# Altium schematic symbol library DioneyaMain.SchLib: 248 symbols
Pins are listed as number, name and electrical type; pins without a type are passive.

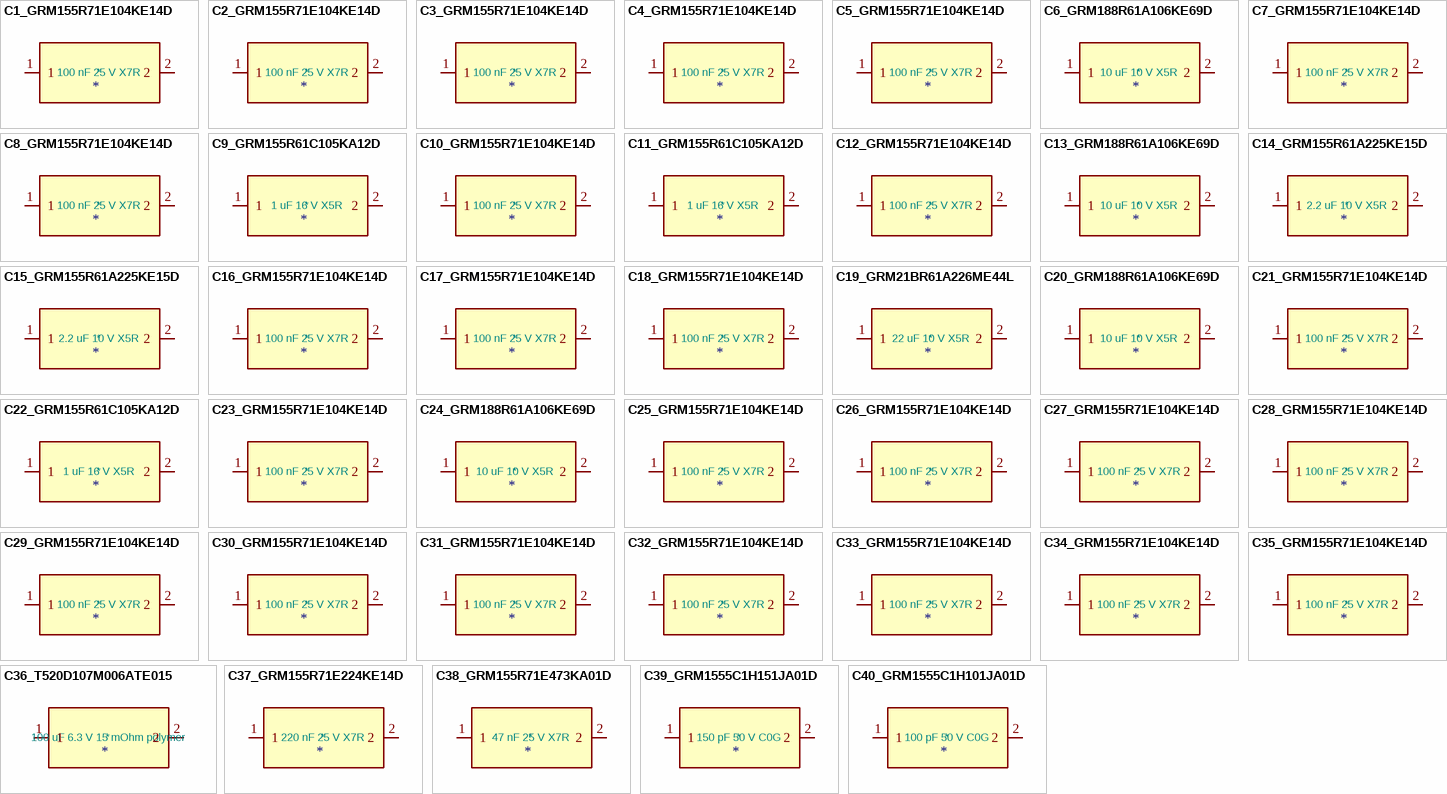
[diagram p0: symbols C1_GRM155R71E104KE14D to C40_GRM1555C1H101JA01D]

## C1_GRM155R71E104KE14D
designator *  value 100 nF 25 V X7R
footprint C_0402_1005Metric
pins: 1, 2

## C2_GRM155R71E104KE14D
designator *  value 100 nF 25 V X7R
footprint C_0402_1005Metric
pins: 1, 2

## C3_GRM155R71E104KE14D
designator *  value 100 nF 25 V X7R
footprint C_0402_1005Metric
pins: 1, 2

## C4_GRM155R71E104KE14D
designator *  value 100 nF 25 V X7R
footprint C_0402_1005Metric
pins: 1, 2

## C5_GRM155R71E104KE14D
designator *  value 100 nF 25 V X7R
footprint C_0402_1005Metric
pins: 1, 2

## C6_GRM188R61A106KE69D
designator *  value 10 uF 10 V X5R
footprint C_0603_1608Metric
pins: 1, 2

## C7_GRM155R71E104KE14D
designator *  value 100 nF 25 V X7R
footprint C_0402_1005Metric
pins: 1, 2

## C8_GRM155R71E104KE14D
designator *  value 100 nF 25 V X7R
footprint C_0402_1005Metric
pins: 1, 2

## C9_GRM155R61C105KA12D
designator *  value 1 uF 16 V X5R
footprint C_0402_1005Metric
pins: 1, 2

## C10_GRM155R71E104KE14D
designator *  value 100 nF 25 V X7R
footprint C_0402_1005Metric
pins: 1, 2

## C11_GRM155R61C105KA12D
designator *  value 1 uF 16 V X5R
footprint C_0402_1005Metric
pins: 1, 2

## C12_GRM155R71E104KE14D
designator *  value 100 nF 25 V X7R
footprint C_0402_1005Metric
pins: 1, 2

## C13_GRM188R61A106KE69D
designator *  value 10 uF 10 V X5R
footprint C_0603_1608Metric
pins: 1, 2

## C14_GRM155R61A225KE15D
designator *  value 2.2 uF 10 V X5R
footprint C_0402_1005Metric
pins: 1, 2

## C15_GRM155R61A225KE15D
designator *  value 2.2 uF 10 V X5R
footprint C_0402_1005Metric
pins: 1, 2

## C16_GRM155R71E104KE14D
designator *  value 100 nF 25 V X7R
footprint C_0402_1005Metric
pins: 1, 2

## C17_GRM155R71E104KE14D
designator *  value 100 nF 25 V X7R
footprint C_0402_1005Metric
pins: 1, 2

## C18_GRM155R71E104KE14D
designator *  value 100 nF 25 V X7R
footprint C_0402_1005Metric
pins: 1, 2

## C19_GRM21BR61A226ME44L
designator *  value 22 uF 10 V X5R
footprint C_0805_2012Metric
pins: 1, 2

## C20_GRM188R61A106KE69D
designator *  value 10 uF 10 V X5R
footprint C_0603_1608Metric
pins: 1, 2

## C21_GRM155R71E104KE14D
designator *  value 100 nF 25 V X7R
footprint C_0402_1005Metric
pins: 1, 2

## C22_GRM155R61C105KA12D
designator *  value 1 uF 16 V X5R
footprint C_0402_1005Metric
pins: 1, 2

## C23_GRM155R71E104KE14D
designator *  value 100 nF 25 V X7R
footprint C_0402_1005Metric
pins: 1, 2

## C24_GRM188R61A106KE69D
designator *  value 10 uF 10 V X5R
footprint C_0603_1608Metric
pins: 1, 2

## C25_GRM155R71E104KE14D
designator *  value 100 nF 25 V X7R
footprint C_0402_1005Metric
pins: 1, 2

## C26_GRM155R71E104KE14D
designator *  value 100 nF 25 V X7R
footprint C_0402_1005Metric
pins: 1, 2

## C27_GRM155R71E104KE14D
designator *  value 100 nF 25 V X7R
footprint C_0402_1005Metric
pins: 1, 2

## C28_GRM155R71E104KE14D
designator *  value 100 nF 25 V X7R
footprint C_0402_1005Metric
pins: 1, 2

## C29_GRM155R71E104KE14D
designator *  value 100 nF 25 V X7R
footprint C_0402_1005Metric
pins: 1, 2

## C30_GRM155R71E104KE14D
designator *  value 100 nF 25 V X7R
footprint C_0402_1005Metric
pins: 1, 2

## C31_GRM155R71E104KE14D
designator *  value 100 nF 25 V X7R
footprint C_0402_1005Metric
pins: 1, 2

## C32_GRM155R71E104KE14D
designator *  value 100 nF 25 V X7R
footprint C_0402_1005Metric
pins: 1, 2

## C33_GRM155R71E104KE14D
designator *  value 100 nF 25 V X7R
footprint C_0402_1005Metric
pins: 1, 2

## C34_GRM155R71E104KE14D
designator *  value 100 nF 25 V X7R
footprint C_0402_1005Metric
pins: 1, 2

## C35_GRM155R71E104KE14D
designator *  value 100 nF 25 V X7R
footprint C_0402_1005Metric
pins: 1, 2

## C36_T520D107M006ATE015
designator *  value 100 uF 6.3 V 15 mOhm polymer
pins: 1, 2

## C37_GRM155R71E224KE14D
designator *  value 220 nF 25 V X7R
footprint C_0402_1005Metric
pins: 1, 2

## C38_GRM155R71E473KA01D
designator *  value 47 nF 25 V X7R
footprint C_0402_1005Metric
pins: 1, 2

## C39_GRM1555C1H151JA01D
designator *  value 150 pF 50 V C0G
footprint C_0402_1005Metric
pins: 1, 2

## C40_GRM1555C1H101JA01D
designator *  value 100 pF 50 V C0G
footprint C_0402_1005Metric
pins: 1, 2

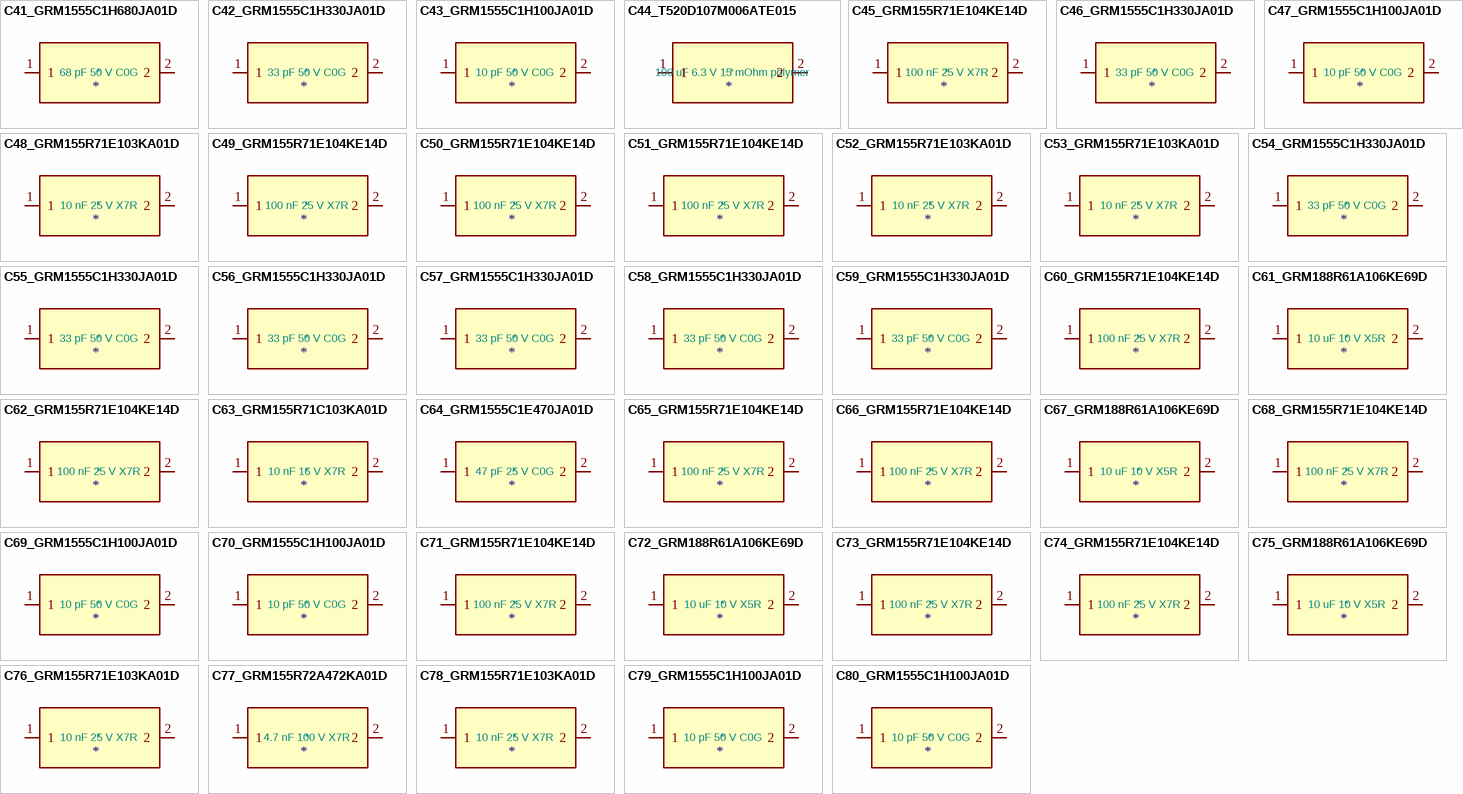
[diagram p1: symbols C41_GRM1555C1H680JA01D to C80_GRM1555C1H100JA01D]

## C41_GRM1555C1H680JA01D
designator *  value 68 pF 50 V C0G
footprint C_0402_1005Metric
pins: 1, 2

## C42_GRM1555C1H330JA01D
designator *  value 33 pF 50 V C0G
footprint C_0402_1005Metric
pins: 1, 2

## C43_GRM1555C1H100JA01D
designator *  value 10 pF 50 V C0G
footprint C_0402_1005Metric
pins: 1, 2

## C44_T520D107M006ATE015
designator *  value 100 uF 6.3 V 15 mOhm polymer
pins: 1, 2

## C45_GRM155R71E104KE14D
designator *  value 100 nF 25 V X7R
footprint C_0402_1005Metric
pins: 1, 2

## C46_GRM1555C1H330JA01D
designator *  value 33 pF 50 V C0G
footprint C_0402_1005Metric
pins: 1, 2

## C47_GRM1555C1H100JA01D
designator *  value 10 pF 50 V C0G
footprint C_0402_1005Metric
pins: 1, 2

## C48_GRM155R71E103KA01D
designator *  value 10 nF 25 V X7R
footprint C_0402_1005Metric
pins: 1, 2

## C49_GRM155R71E104KE14D
designator *  value 100 nF 25 V X7R
footprint C_0402_1005Metric
pins: 1, 2

## C50_GRM155R71E104KE14D
designator *  value 100 nF 25 V X7R
footprint C_0402_1005Metric
pins: 1, 2

## C51_GRM155R71E104KE14D
designator *  value 100 nF 25 V X7R
footprint C_0402_1005Metric
pins: 1, 2

## C52_GRM155R71E103KA01D
designator *  value 10 nF 25 V X7R
footprint C_0402_1005Metric
pins: 1, 2

## C53_GRM155R71E103KA01D
designator *  value 10 nF 25 V X7R
footprint C_0402_1005Metric
pins: 1, 2

## C54_GRM1555C1H330JA01D
designator *  value 33 pF 50 V C0G
footprint C_0402_1005Metric
pins: 1, 2

## C55_GRM1555C1H330JA01D
designator *  value 33 pF 50 V C0G
footprint C_0402_1005Metric
pins: 1, 2

## C56_GRM1555C1H330JA01D
designator *  value 33 pF 50 V C0G
footprint C_0402_1005Metric
pins: 1, 2

## C57_GRM1555C1H330JA01D
designator *  value 33 pF 50 V C0G
footprint C_0402_1005Metric
pins: 1, 2

## C58_GRM1555C1H330JA01D
designator *  value 33 pF 50 V C0G
footprint C_0402_1005Metric
pins: 1, 2

## C59_GRM1555C1H330JA01D
designator *  value 33 pF 50 V C0G
footprint C_0402_1005Metric
pins: 1, 2

## C60_GRM155R71E104KE14D
designator *  value 100 nF 25 V X7R
footprint C_0402_1005Metric
pins: 1, 2

## C61_GRM188R61A106KE69D
designator *  value 10 uF 10 V X5R
footprint C_0603_1608Metric
pins: 1, 2

## C62_GRM155R71E104KE14D
designator *  value 100 nF 25 V X7R
footprint C_0402_1005Metric
pins: 1, 2

## C63_GRM155R71C103KA01D
designator *  value 10 nF 16 V X7R
footprint C_0402_1005Metric
pins: 1, 2

## C64_GRM1555C1E470JA01D
designator *  value 47 pF 25 V C0G
footprint C_0402_1005Metric
pins: 1, 2

## C65_GRM155R71E104KE14D
designator *  value 100 nF 25 V X7R
footprint C_0402_1005Metric
pins: 1, 2

## C66_GRM155R71E104KE14D
designator *  value 100 nF 25 V X7R
footprint C_0402_1005Metric
pins: 1, 2

## C67_GRM188R61A106KE69D
designator *  value 10 uF 10 V X5R
footprint C_0603_1608Metric
pins: 1, 2

## C68_GRM155R71E104KE14D
designator *  value 100 nF 25 V X7R
footprint C_0402_1005Metric
pins: 1, 2

## C69_GRM1555C1H100JA01D
designator *  value 10 pF 50 V C0G
footprint C_0402_1005Metric
pins: 1, 2

## C70_GRM1555C1H100JA01D
designator *  value 10 pF 50 V C0G
footprint C_0402_1005Metric
pins: 1, 2

## C71_GRM155R71E104KE14D
designator *  value 100 nF 25 V X7R
footprint C_0402_1005Metric
pins: 1, 2

## C72_GRM188R61A106KE69D
designator *  value 10 uF 10 V X5R
footprint C_0603_1608Metric
pins: 1, 2

## C73_GRM155R71E104KE14D
designator *  value 100 nF 25 V X7R
footprint C_0402_1005Metric
pins: 1, 2

## C74_GRM155R71E104KE14D
designator *  value 100 nF 25 V X7R
footprint C_0402_1005Metric
pins: 1, 2

## C75_GRM188R61A106KE69D
designator *  value 10 uF 10 V X5R
footprint C_0603_1608Metric
pins: 1, 2

## C76_GRM155R71E103KA01D
designator *  value 10 nF 25 V X7R
footprint C_0402_1005Metric
pins: 1, 2

## C77_GRM155R72A472KA01D
designator *  value 4.7 nF 100 V X7R
footprint C_0402_1005Metric
pins: 1, 2

## C78_GRM155R71E103KA01D
designator *  value 10 nF 25 V X7R
footprint C_0402_1005Metric
pins: 1, 2

## C79_GRM1555C1H100JA01D
designator *  value 10 pF 50 V C0G
footprint C_0402_1005Metric
pins: 1, 2

## C80_GRM1555C1H100JA01D
designator *  value 10 pF 50 V C0G
footprint C_0402_1005Metric
pins: 1, 2

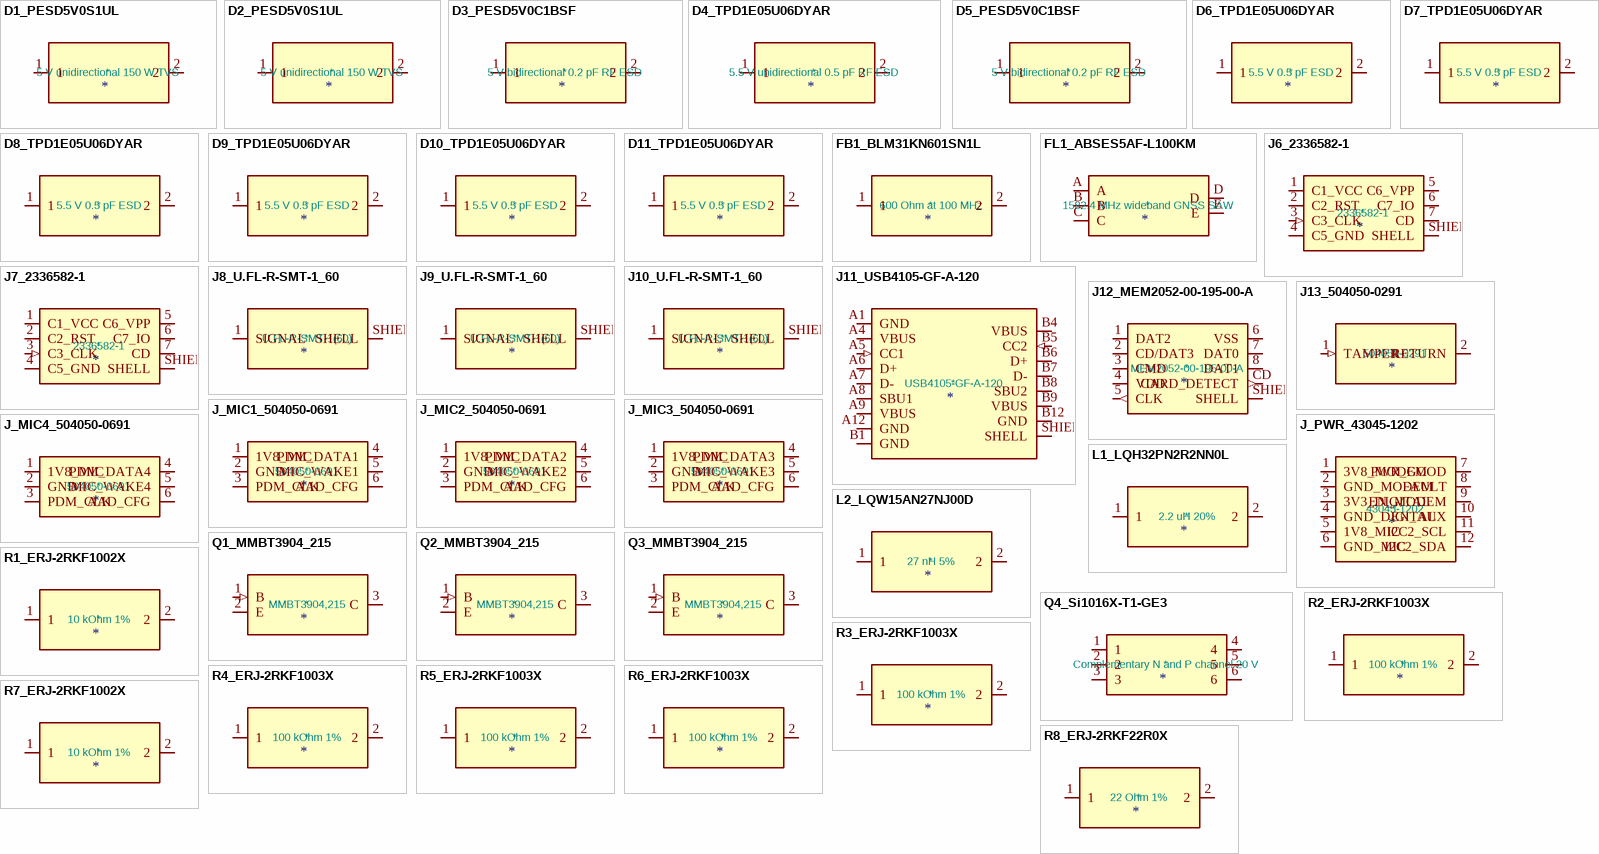
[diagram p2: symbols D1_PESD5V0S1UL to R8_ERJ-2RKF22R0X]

## D1_PESD5V0S1UL
designator *  value 5 V unidirectional 150 W TVS
pins: 1, 2

## D2_PESD5V0S1UL
designator *  value 5 V unidirectional 150 W TVS
pins: 1, 2

## D3_PESD5V0C1BSF
designator *  value 5 V bidirectional 0.2 pF RF ESD
pins: 1, 2

## D4_TPD1E05U06DYAR
designator *  value 5.5 V unidirectional 0.5 pF RF ESD
pins: 1, 2

## D5_PESD5V0C1BSF
designator *  value 5 V bidirectional 0.2 pF RF ESD
pins: 1, 2

## D6_TPD1E05U06DYAR
designator *  value 5.5 V 0.5 pF ESD
pins: 1, 2

## D7_TPD1E05U06DYAR
designator *  value 5.5 V 0.5 pF ESD
pins: 1, 2

## D8_TPD1E05U06DYAR
designator *  value 5.5 V 0.5 pF ESD
pins: 1, 2

## D9_TPD1E05U06DYAR
designator *  value 5.5 V 0.5 pF ESD
pins: 1, 2

## D10_TPD1E05U06DYAR
designator *  value 5.5 V 0.5 pF ESD
pins: 1, 2

## D11_TPD1E05U06DYAR
designator *  value 5.5 V 0.5 pF ESD
pins: 1, 2

## FB1_BLM31KN601SN1L
designator *  value 600 Ohm at 100 MHz
footprint L_1206_3216Metric
pins: 1, 2

## FL1_ABSES5AF-L100KM
designator *  value 1582.4 MHz wideband GNSS SAW
pins: A, B, C, D, E

## J6_2336582-1
designator *  value 2336582-1
pins: 1 C1_VCC, 2 C2_RST (io), 3 C3_CLK (in), 4 C5_GND, 5 C6_VPP, 6 C7_IO (io), 7 CD (io), SHIELD SHELL

## J7_2336582-1
designator *  value 2336582-1
pins: 1 C1_VCC, 2 C2_RST (io), 3 C3_CLK (in), 4 C5_GND, 5 C6_VPP, 6 C7_IO (io), 7 CD (io), SHIELD SHELL

## J8_U.FL-R-SMT-1_60
designator *  value U.FL-R-SMT-1(60)
pins: 1 SIGNAL (io), SHIELD SHELL

## J9_U.FL-R-SMT-1_60
designator *  value U.FL-R-SMT-1(60)
pins: 1 SIGNAL (io), SHIELD SHELL

## J10_U.FL-R-SMT-1_60
designator *  value U.FL-R-SMT-1(60)
pins: 1 SIGNAL (io), SHIELD SHELL

## J11_USB4105-GF-A-120
designator *  value USB4105-GF-A-120
pins: A1 GND, A4 VBUS, A5 CC1 (in), A6 D+ (io), A7 D- (io), A8 SBU1, A9 VBUS, A12 GND, B1 GND, B4 VBUS, B5 CC2 (in), B6 D+ (io), B7 D- (io), B8 SBU2, B9 VBUS, B12 GND, SHIELD SHELL

## J12_MEM2052-00-195-00-A
designator *  value MEM2052-00-195-00-A
pins: 1 DAT2 (io), 2 CD/DAT3 (io), 3 CMD (io), 4 VDD, 5 CLK (out), 6 VSS, 7 DAT0 (io), 8 DAT1 (io), CD CARD_DETECT (out), SHIELD SHELL

## J13_504050-0291
designator *  value 504050-0291
pins: 1 TAMPER (in), 2 RETURN

## J_MIC1_504050-0691
designator *  value 504050-0691
pins: 1 1V8_MIC, 2 GND, 3 PDM_CLK, 4 PDM_DATA1, 5 MIC_WAKE1, 6 AAD_CFG

## J_MIC2_504050-0691
designator *  value 504050-0691
pins: 1 1V8_MIC, 2 GND, 3 PDM_CLK, 4 PDM_DATA2, 5 MIC_WAKE2, 6 AAD_CFG

## J_MIC3_504050-0691
designator *  value 504050-0691
pins: 1 1V8_MIC, 2 GND, 3 PDM_CLK, 4 PDM_DATA3, 5 MIC_WAKE3, 6 AAD_CFG

## J_MIC4_504050-0691
designator *  value 504050-0691
pins: 1 1V8_MIC, 2 GND, 3 PDM_CLK, 4 PDM_DATA4, 5 MIC_WAKE4, 6 AAD_CFG

## J_PWR_43045-1202
designator *  value 43045-1202
pins: 1 3V8_MODEM, 2 GND_MODEM, 3 3V3_DIGITAL, 4 GND_DIGITAL, 5 1V8_MIC, 6 GND_MIC, 7 PWR_GOOD, 8 FAULT, 9 EN_MODEM, 10 EN_AUX, 11 I2C2_SCL (io), 12 I2C2_SDA (io)

## L1_LQH32PN2R2NN0L
designator *  value 2.2 uH 20%
footprint L_1210_3225Metric
pins: 1, 2

## L2_LQW15AN27NJ00D
designator *  value 27 nH 5%
footprint L_0402_1005Metric
pins: 1, 2

## Q1_MMBT3904_215
designator *  value MMBT3904,215
pins: 1 B (in), 2 E, 3 C (oc)

## Q2_MMBT3904_215
designator *  value MMBT3904,215
pins: 1 B (in), 2 E, 3 C (oc)

## Q3_MMBT3904_215
designator *  value MMBT3904,215
pins: 1 B (in), 2 E, 3 C (oc)

## Q4_Si1016X-T1-GE3
designator *  value Complementary N and P channel 20 V
pins: 1, 2, 3, 4, 5, 6

## R1_ERJ-2RKF1002X
designator *  value 10 kOhm 1%
footprint R_0402_1005Metric
pins: 1, 2

## R2_ERJ-2RKF1003X
designator *  value 100 kOhm 1%
footprint R_0402_1005Metric
pins: 1, 2

## R3_ERJ-2RKF1003X
designator *  value 100 kOhm 1%
footprint R_0402_1005Metric
pins: 1, 2

## R4_ERJ-2RKF1003X
designator *  value 100 kOhm 1%
footprint R_0402_1005Metric
pins: 1, 2

## R5_ERJ-2RKF1003X
designator *  value 100 kOhm 1%
footprint R_0402_1005Metric
pins: 1, 2

## R6_ERJ-2RKF1003X
designator *  value 100 kOhm 1%
footprint R_0402_1005Metric
pins: 1, 2

## R7_ERJ-2RKF1002X
designator *  value 10 kOhm 1%
footprint R_0402_1005Metric
pins: 1, 2

## R8_ERJ-2RKF22R0X
designator *  value 22 Ohm 1%
footprint R_0402_1005Metric
pins: 1, 2

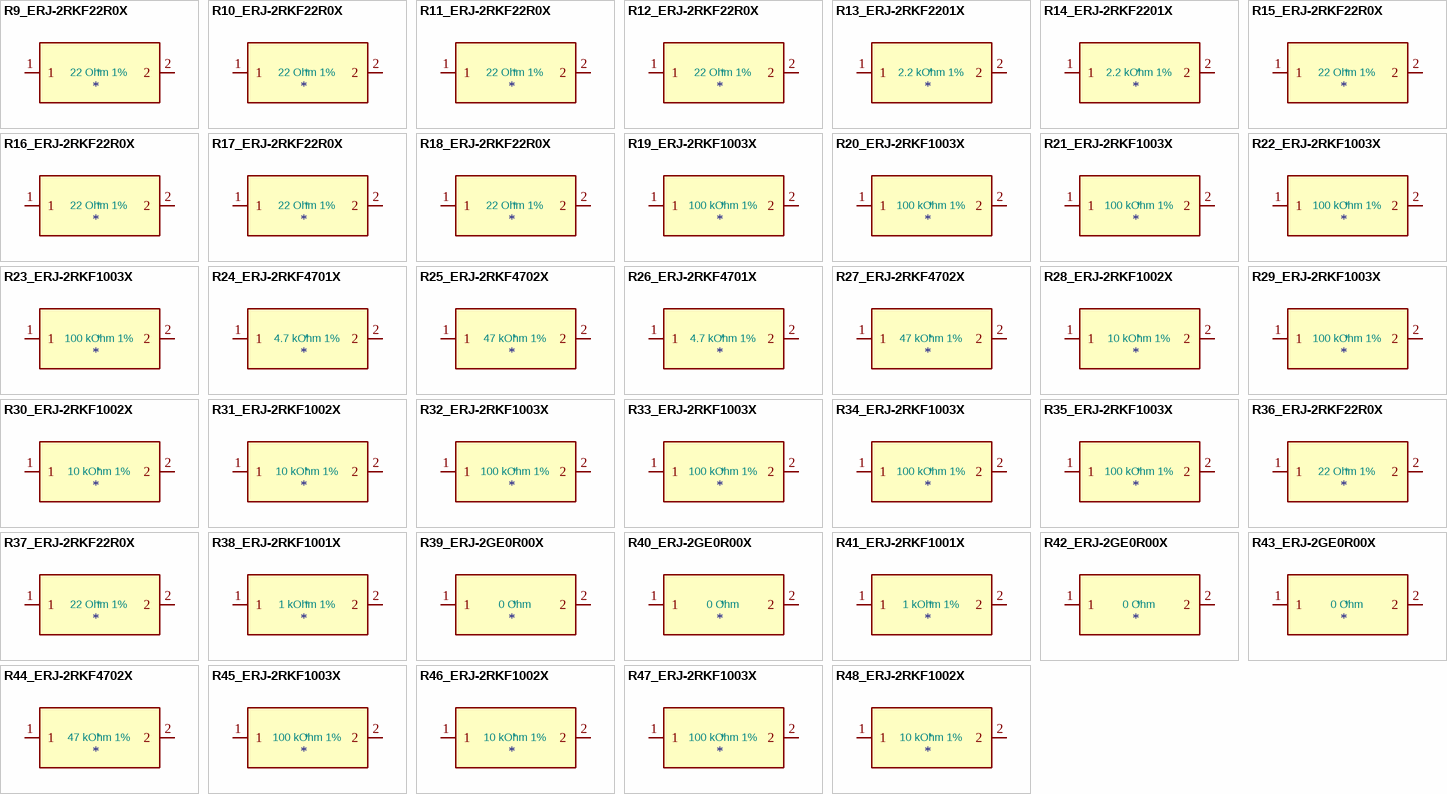
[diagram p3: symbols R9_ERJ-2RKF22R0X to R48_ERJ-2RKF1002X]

## R9_ERJ-2RKF22R0X
designator *  value 22 Ohm 1%
footprint R_0402_1005Metric
pins: 1, 2

## R10_ERJ-2RKF22R0X
designator *  value 22 Ohm 1%
footprint R_0402_1005Metric
pins: 1, 2

## R11_ERJ-2RKF22R0X
designator *  value 22 Ohm 1%
footprint R_0402_1005Metric
pins: 1, 2

## R12_ERJ-2RKF22R0X
designator *  value 22 Ohm 1%
footprint R_0402_1005Metric
pins: 1, 2

## R13_ERJ-2RKF2201X
designator *  value 2.2 kOhm 1%
footprint R_0402_1005Metric
pins: 1, 2

## R14_ERJ-2RKF2201X
designator *  value 2.2 kOhm 1%
footprint R_0402_1005Metric
pins: 1, 2

## R15_ERJ-2RKF22R0X
designator *  value 22 Ohm 1%
footprint R_0402_1005Metric
pins: 1, 2

## R16_ERJ-2RKF22R0X
designator *  value 22 Ohm 1%
footprint R_0402_1005Metric
pins: 1, 2

## R17_ERJ-2RKF22R0X
designator *  value 22 Ohm 1%
footprint R_0402_1005Metric
pins: 1, 2

## R18_ERJ-2RKF22R0X
designator *  value 22 Ohm 1%
footprint R_0402_1005Metric
pins: 1, 2

## R19_ERJ-2RKF1003X
designator *  value 100 kOhm 1%
footprint R_0402_1005Metric
pins: 1, 2

## R20_ERJ-2RKF1003X
designator *  value 100 kOhm 1%
footprint R_0402_1005Metric
pins: 1, 2

## R21_ERJ-2RKF1003X
designator *  value 100 kOhm 1%
footprint R_0402_1005Metric
pins: 1, 2

## R22_ERJ-2RKF1003X
designator *  value 100 kOhm 1%
footprint R_0402_1005Metric
pins: 1, 2

## R23_ERJ-2RKF1003X
designator *  value 100 kOhm 1%
footprint R_0402_1005Metric
pins: 1, 2

## R24_ERJ-2RKF4701X
designator *  value 4.7 kOhm 1%
footprint R_0402_1005Metric
pins: 1, 2

## R25_ERJ-2RKF4702X
designator *  value 47 kOhm 1%
footprint R_0402_1005Metric
pins: 1, 2

## R26_ERJ-2RKF4701X
designator *  value 4.7 kOhm 1%
footprint R_0402_1005Metric
pins: 1, 2

## R27_ERJ-2RKF4702X
designator *  value 47 kOhm 1%
footprint R_0402_1005Metric
pins: 1, 2

## R28_ERJ-2RKF1002X
designator *  value 10 kOhm 1%
footprint R_0402_1005Metric
pins: 1, 2

## R29_ERJ-2RKF1003X
designator *  value 100 kOhm 1%
footprint R_0402_1005Metric
pins: 1, 2

## R30_ERJ-2RKF1002X
designator *  value 10 kOhm 1%
footprint R_0402_1005Metric
pins: 1, 2

## R31_ERJ-2RKF1002X
designator *  value 10 kOhm 1%
footprint R_0402_1005Metric
pins: 1, 2

## R32_ERJ-2RKF1003X
designator *  value 100 kOhm 1%
footprint R_0402_1005Metric
pins: 1, 2

## R33_ERJ-2RKF1003X
designator *  value 100 kOhm 1%
footprint R_0402_1005Metric
pins: 1, 2

## R34_ERJ-2RKF1003X
designator *  value 100 kOhm 1%
footprint R_0402_1005Metric
pins: 1, 2

## R35_ERJ-2RKF1003X
designator *  value 100 kOhm 1%
footprint R_0402_1005Metric
pins: 1, 2

## R36_ERJ-2RKF22R0X
designator *  value 22 Ohm 1%
footprint R_0402_1005Metric
pins: 1, 2

## R37_ERJ-2RKF22R0X
designator *  value 22 Ohm 1%
footprint R_0402_1005Metric
pins: 1, 2

## R38_ERJ-2RKF1001X
designator *  value 1 kOhm 1%
footprint R_0402_1005Metric
pins: 1, 2

## R39_ERJ-2GE0R00X
designator *  value 0 Ohm
footprint R_0402_1005Metric
pins: 1, 2

## R40_ERJ-2GE0R00X
designator *  value 0 Ohm
footprint R_0402_1005Metric
pins: 1, 2

## R41_ERJ-2RKF1001X
designator *  value 1 kOhm 1%
footprint R_0402_1005Metric
pins: 1, 2

## R42_ERJ-2GE0R00X
designator *  value 0 Ohm
footprint R_0402_1005Metric
pins: 1, 2

## R43_ERJ-2GE0R00X
designator *  value 0 Ohm
footprint R_0402_1005Metric
pins: 1, 2

## R44_ERJ-2RKF4702X
designator *  value 47 kOhm 1%
footprint R_0402_1005Metric
pins: 1, 2

## R45_ERJ-2RKF1003X
designator *  value 100 kOhm 1%
footprint R_0402_1005Metric
pins: 1, 2

## R46_ERJ-2RKF1002X
designator *  value 10 kOhm 1%
footprint R_0402_1005Metric
pins: 1, 2

## R47_ERJ-2RKF1003X
designator *  value 100 kOhm 1%
footprint R_0402_1005Metric
pins: 1, 2

## R48_ERJ-2RKF1002X
designator *  value 10 kOhm 1%
footprint R_0402_1005Metric
pins: 1, 2

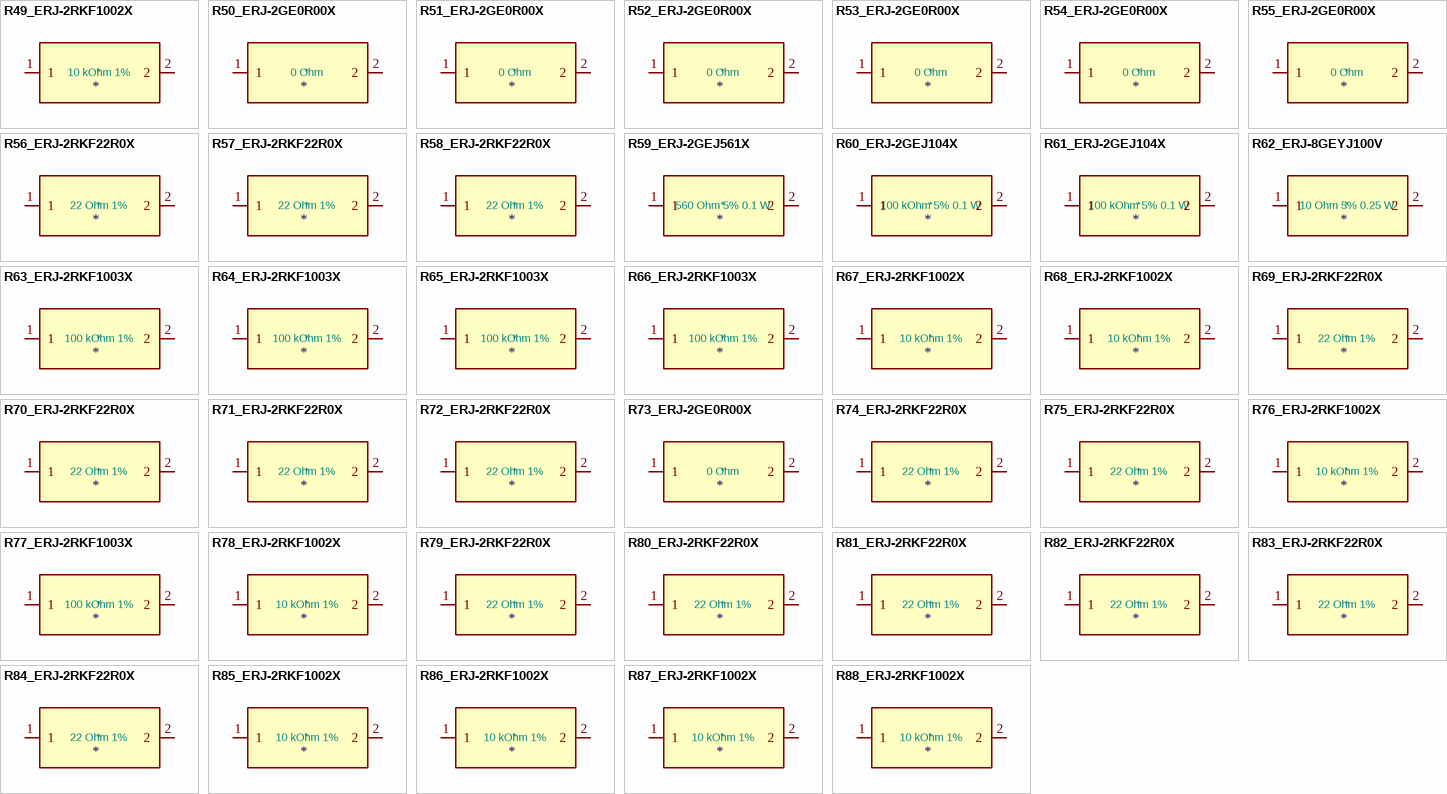
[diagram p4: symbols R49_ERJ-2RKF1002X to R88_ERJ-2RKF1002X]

## R49_ERJ-2RKF1002X
designator *  value 10 kOhm 1%
footprint R_0402_1005Metric
pins: 1, 2

## R50_ERJ-2GE0R00X
designator *  value 0 Ohm
footprint R_0402_1005Metric
pins: 1, 2

## R51_ERJ-2GE0R00X
designator *  value 0 Ohm
footprint R_0402_1005Metric
pins: 1, 2

## R52_ERJ-2GE0R00X
designator *  value 0 Ohm
footprint R_0402_1005Metric
pins: 1, 2

## R53_ERJ-2GE0R00X
designator *  value 0 Ohm
footprint R_0402_1005Metric
pins: 1, 2

## R54_ERJ-2GE0R00X
designator *  value 0 Ohm
footprint R_0402_1005Metric
pins: 1, 2

## R55_ERJ-2GE0R00X
designator *  value 0 Ohm
footprint R_0402_1005Metric
pins: 1, 2

## R56_ERJ-2RKF22R0X
designator *  value 22 Ohm 1%
footprint R_0402_1005Metric
pins: 1, 2

## R57_ERJ-2RKF22R0X
designator *  value 22 Ohm 1%
footprint R_0402_1005Metric
pins: 1, 2

## R58_ERJ-2RKF22R0X
designator *  value 22 Ohm 1%
footprint R_0402_1005Metric
pins: 1, 2

## R59_ERJ-2GEJ561X
designator *  value 560 Ohm 5% 0.1 W
footprint R_0402_1005Metric
pins: 1, 2

## R60_ERJ-2GEJ104X
designator *  value 100 kOhm 5% 0.1 W
footprint R_0402_1005Metric
pins: 1, 2

## R61_ERJ-2GEJ104X
designator *  value 100 kOhm 5% 0.1 W
footprint R_0402_1005Metric
pins: 1, 2

## R62_ERJ-8GEYJ100V
designator *  value 10 Ohm 5% 0.25 W
footprint R_1206_3216Metric
pins: 1, 2

## R63_ERJ-2RKF1003X
designator *  value 100 kOhm 1%
footprint R_0402_1005Metric
pins: 1, 2

## R64_ERJ-2RKF1003X
designator *  value 100 kOhm 1%
footprint R_0402_1005Metric
pins: 1, 2

## R65_ERJ-2RKF1003X
designator *  value 100 kOhm 1%
footprint R_0402_1005Metric
pins: 1, 2

## R66_ERJ-2RKF1003X
designator *  value 100 kOhm 1%
footprint R_0402_1005Metric
pins: 1, 2

## R67_ERJ-2RKF1002X
designator *  value 10 kOhm 1%
footprint R_0402_1005Metric
pins: 1, 2

## R68_ERJ-2RKF1002X
designator *  value 10 kOhm 1%
footprint R_0402_1005Metric
pins: 1, 2

## R69_ERJ-2RKF22R0X
designator *  value 22 Ohm 1%
footprint R_0402_1005Metric
pins: 1, 2

## R70_ERJ-2RKF22R0X
designator *  value 22 Ohm 1%
footprint R_0402_1005Metric
pins: 1, 2

## R71_ERJ-2RKF22R0X
designator *  value 22 Ohm 1%
footprint R_0402_1005Metric
pins: 1, 2

## R72_ERJ-2RKF22R0X
designator *  value 22 Ohm 1%
footprint R_0402_1005Metric
pins: 1, 2

## R73_ERJ-2GE0R00X
designator *  value 0 Ohm
footprint R_0402_1005Metric
pins: 1, 2

## R74_ERJ-2RKF22R0X
designator *  value 22 Ohm 1%
footprint R_0402_1005Metric
pins: 1, 2

## R75_ERJ-2RKF22R0X
designator *  value 22 Ohm 1%
footprint R_0402_1005Metric
pins: 1, 2

## R76_ERJ-2RKF1002X
designator *  value 10 kOhm 1%
footprint R_0402_1005Metric
pins: 1, 2

## R77_ERJ-2RKF1003X
designator *  value 100 kOhm 1%
footprint R_0402_1005Metric
pins: 1, 2

## R78_ERJ-2RKF1002X
designator *  value 10 kOhm 1%
footprint R_0402_1005Metric
pins: 1, 2

## R79_ERJ-2RKF22R0X
designator *  value 22 Ohm 1%
footprint R_0402_1005Metric
pins: 1, 2

## R80_ERJ-2RKF22R0X
designator *  value 22 Ohm 1%
footprint R_0402_1005Metric
pins: 1, 2

## R81_ERJ-2RKF22R0X
designator *  value 22 Ohm 1%
footprint R_0402_1005Metric
pins: 1, 2

## R82_ERJ-2RKF22R0X
designator *  value 22 Ohm 1%
footprint R_0402_1005Metric
pins: 1, 2

## R83_ERJ-2RKF22R0X
designator *  value 22 Ohm 1%
footprint R_0402_1005Metric
pins: 1, 2

## R84_ERJ-2RKF22R0X
designator *  value 22 Ohm 1%
footprint R_0402_1005Metric
pins: 1, 2

## R85_ERJ-2RKF1002X
designator *  value 10 kOhm 1%
footprint R_0402_1005Metric
pins: 1, 2

## R86_ERJ-2RKF1002X
designator *  value 10 kOhm 1%
footprint R_0402_1005Metric
pins: 1, 2

## R87_ERJ-2RKF1002X
designator *  value 10 kOhm 1%
footprint R_0402_1005Metric
pins: 1, 2

## R88_ERJ-2RKF1002X
designator *  value 10 kOhm 1%
footprint R_0402_1005Metric
pins: 1, 2

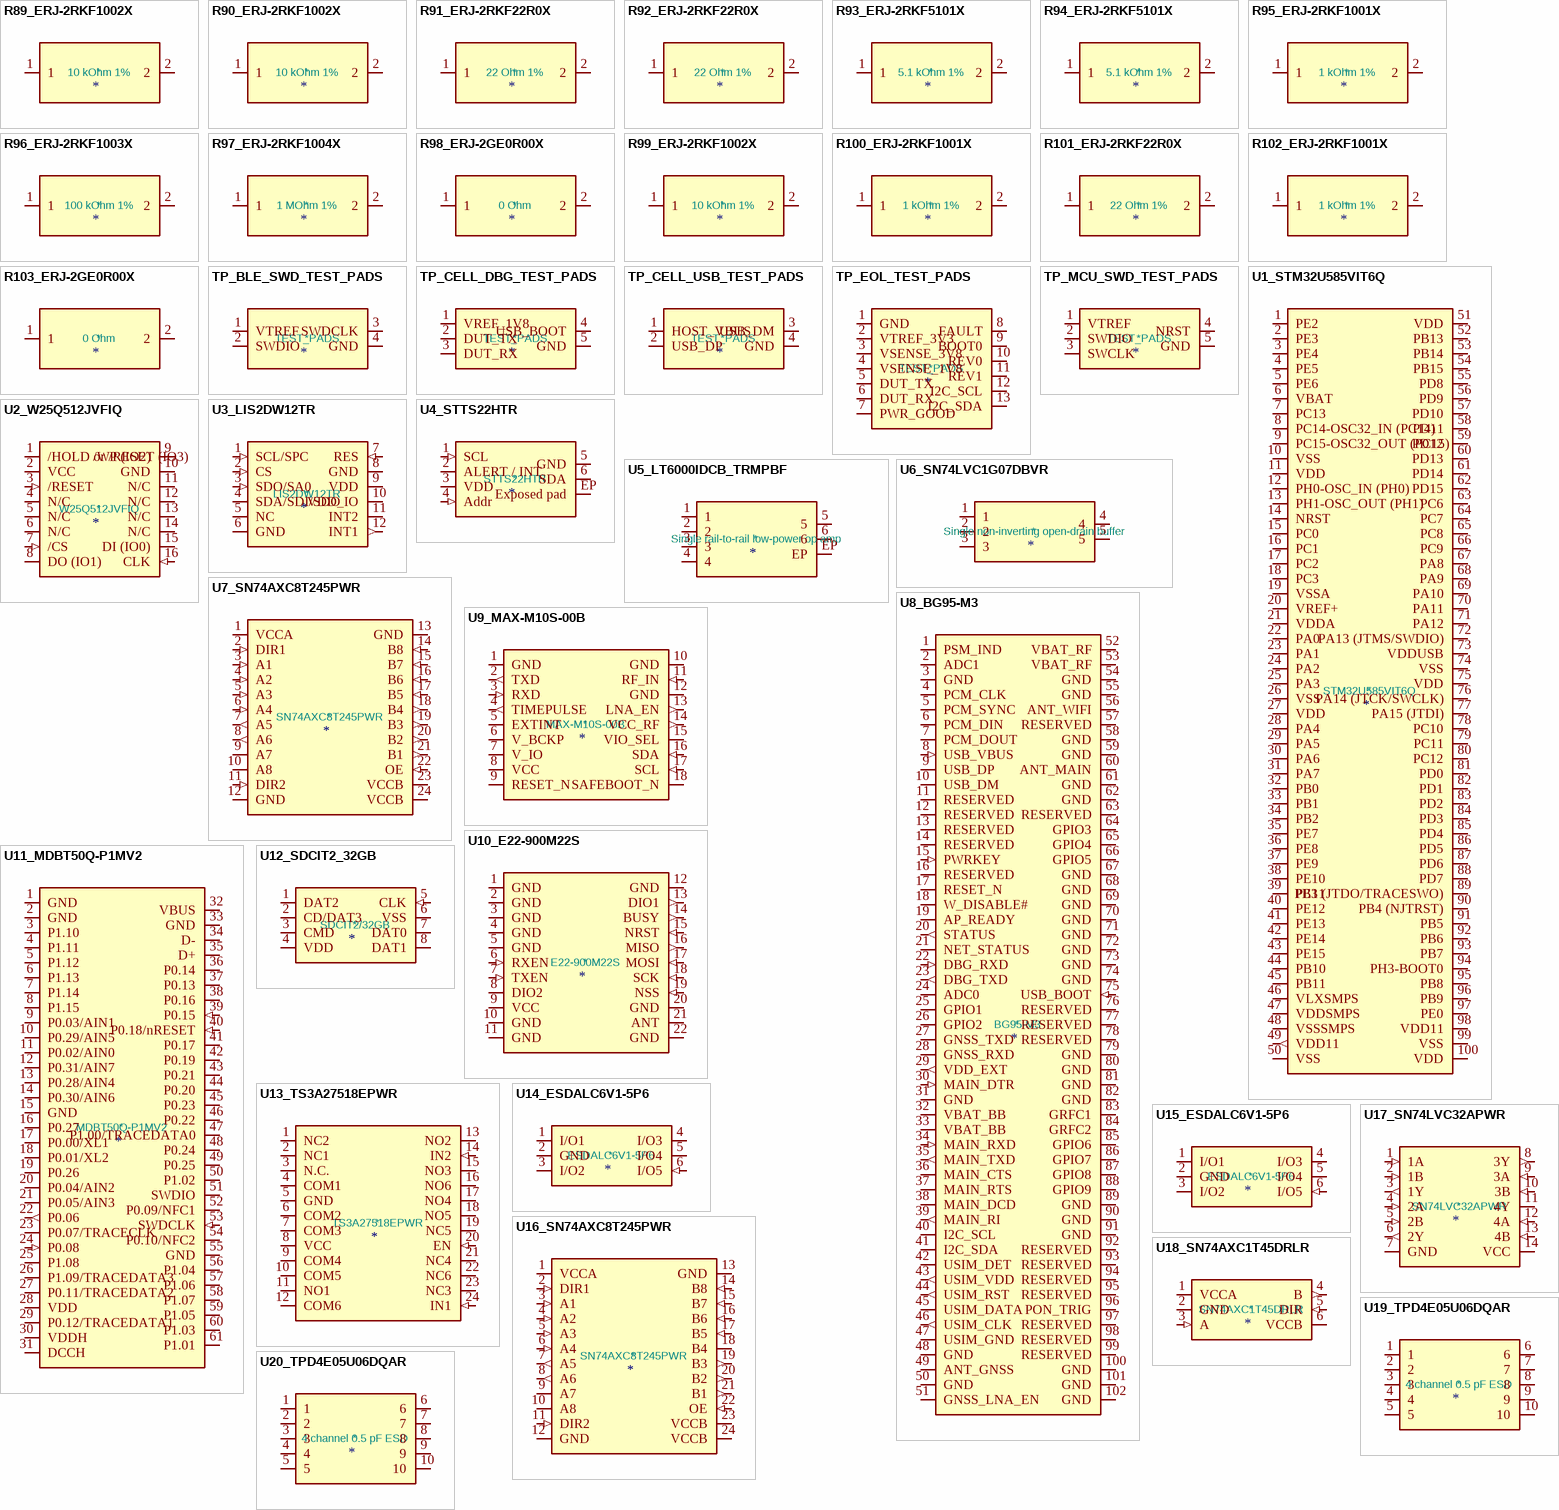
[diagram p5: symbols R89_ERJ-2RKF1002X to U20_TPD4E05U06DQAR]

## R89_ERJ-2RKF1002X
designator *  value 10 kOhm 1%
footprint R_0402_1005Metric
pins: 1, 2

## R90_ERJ-2RKF1002X
designator *  value 10 kOhm 1%
footprint R_0402_1005Metric
pins: 1, 2

## R91_ERJ-2RKF22R0X
designator *  value 22 Ohm 1%
footprint R_0402_1005Metric
pins: 1, 2

## R92_ERJ-2RKF22R0X
designator *  value 22 Ohm 1%
footprint R_0402_1005Metric
pins: 1, 2

## R93_ERJ-2RKF5101X
designator *  value 5.1 kOhm 1%
footprint R_0402_1005Metric
pins: 1, 2

## R94_ERJ-2RKF5101X
designator *  value 5.1 kOhm 1%
footprint R_0402_1005Metric
pins: 1, 2

## R95_ERJ-2RKF1001X
designator *  value 1 kOhm 1%
footprint R_0402_1005Metric
pins: 1, 2

## R96_ERJ-2RKF1003X
designator *  value 100 kOhm 1%
footprint R_0402_1005Metric
pins: 1, 2

## R97_ERJ-2RKF1004X
designator *  value 1 MOhm 1%
footprint R_0402_1005Metric
pins: 1, 2

## R98_ERJ-2GE0R00X
designator *  value 0 Ohm
footprint R_0402_1005Metric
pins: 1, 2

## R99_ERJ-2RKF1002X
designator *  value 10 kOhm 1%
footprint R_0402_1005Metric
pins: 1, 2

## R100_ERJ-2RKF1001X
designator *  value 1 kOhm 1%
footprint R_0402_1005Metric
pins: 1, 2

## R101_ERJ-2RKF22R0X
designator *  value 22 Ohm 1%
footprint R_0402_1005Metric
pins: 1, 2

## R102_ERJ-2RKF1001X
designator *  value 1 kOhm 1%
footprint R_0402_1005Metric
pins: 1, 2

## R103_ERJ-2GE0R00X
designator *  value 0 Ohm
footprint R_0402_1005Metric
pins: 1, 2

## TP_BLE_SWD_TEST_PADS
designator *  value TEST_PADS
pins: 1 VTREF, 2 SWDIO, 3 SWDCLK, 4 GND

## TP_CELL_DBG_TEST_PADS
designator *  value TEST_PADS
pins: 1 VREF_1V8, 2 DUT_TX, 3 DUT_RX, 4 USB_BOOT, 5 GND

## TP_CELL_USB_TEST_PADS
designator *  value TEST_PADS
pins: 1 HOST_VBUS, 2 USB_DP, 3 USB_DM, 4 GND

## TP_EOL_TEST_PADS
designator *  value TEST_PADS
pins: 1 GND, 2 VTREF_3V3, 3 VSENSE_3V8, 4 VSENSE_1V8, 5 DUT_TX, 6 DUT_RX, 7 PWR_GOOD, 8 FAULT, 9 BOOT0, 10 REV0, 11 REV1, 12 I2C_SCL, 13 I2C_SDA

## TP_MCU_SWD_TEST_PADS
designator *  value TEST_PADS
pins: 1 VTREF, 2 SWDIO, 3 SWCLK, 4 NRST, 5 GND

## U1_STM32U585VIT6Q
designator *  value STM32U585VIT6Q
pins: 1 PE2, 2 PE3, 3 PE4, 4 PE5, 5 PE6, 6 VBAT, 7 PC13, 8 PC14-OSC32_IN (PC14), 9 PC15-OSC32_OUT (PC15), 10 VSS, 11 VDD, 12 PH0-OSC_IN (PH0), 13 PH1-OSC_OUT (PH1), 14 NRST, 15 PC0, 16 PC1, 17 PC2, 18 PC3, 19 VSSA, 20 VREF+, 21 VDDA, 22 PA0, 23 PA1, 24 PA2, 25 PA3, 26 VSS, 27 VDD, 28 PA4, 29 PA5, 30 PA6, 31 PA7, 32 PB0, 33 PB1, 34 PB2, 35 PE7, 36 PE8, 37 PE9, 38 PE10, 39 PE11, 40 PE12, 41 PE13, 42 PE14, 43 PE15, 44 PB10, 45 PB11, 46 VLXSMPS, 47 VDDSMPS, 48 VSSSMPS, 49 VDD11 (out), 50 VSS, 51 VDD, 52 PB13, 53 PB14, 54 PB15, 55 PD8, 56 PD9, 57 PD10, 58 PD11, 59 PD12, 60 PD13, 61 PD14, 62 PD15, 63 PC6, 64 PC7, 65 PC8, 66 PC9, 67 PA8, 68 PA9, 69 PA10, 70 PA11, 71 PA12, 72 PA13 (JTMS/SWDIO), 73 VDDUSB, 74 VSS, 75 VDD, 76 PA14 (JTCK/SWCLK), 77 PA15 (JTDI), 78 PC10, 79 PC11, 80 PC12, 81 PD0, 82 PD1, 83 PD2, 84 PD3, 85 PD4, 86 PD5, 87 PD6, 88 PD7, 89 PB3 (JTDO/TRACESWO), 90 PB4 (NJTRST), 91 PB5, 92 PB6, 93 PB7, 94 PH3-BOOT0, 95 PB8, 96 PB9, 97 PE0, 98 VDD11, 99 VSS, 100 VDD

## U2_W25Q512JVFIQ
designator *  value W25Q512JVFIQ
pins: 1 /HOLD or /RESET (IO3) (io), 2 VCC, 3 /RESET (in), 4 N/C, 5 N/C, 6 N/C, 7 /CS (in), 8 DO (IO1) (io), 9 /WP (IO2) (io), 10 GND, 11 N/C, 12 N/C, 13 N/C, 14 N/C, 15 DI (IO0) (io), 16 CLK (in)

## U3_LIS2DW12TR
designator *  value LIS2DW12TR
pins: 1 SCL/SPC (in), 2 CS (in), 3 SDO/SA0 (in), 4 SDA/SDI/SDO (io), 5 NC, 6 GND, 7 RES (in), 8 GND, 9 VDD, 10 VDD_IO, 11 INT2, 12 INT1 (out)

## U4_STTS22HTR
designator *  value STTS22HTR
pins: 1 SCL (in), 2 ALERT / INT, 3 VDD, 4 Addr (in), 5 GND, 6 SDA (io), EP Exposed pad

## U5_LT6000IDCB_TRMPBF
designator *  value Single rail-to-rail low-power op amp
pins: 1, 2, 3, 4, 5, 6, EP

## U6_SN74LVC1G07DBVR
designator *  value Single non-inverting open-drain buffer
pins: 1, 2, 3, 4, 5

## U7_SN74AXC8T245PWR
designator *  value SN74AXC8T245PWR
pins: 1 VCCA, 2 DIR1 (in), 3 A1 (in), 4 A2 (in), 5 A3 (in), 6 A4 (in), 7 A5 (out), 8 A6 (out), 9 A7, 10 A8, 11 DIR2 (in), 12 GND, 13 GND, 14 B8 (in), 15 B7 (in), 16 B6 (in), 17 B5 (in), 18 B4 (out), 19 B3 (out), 20 B2 (out), 21 B1 (out), 22 OE (in), 23 VCCB, 24 VCCB

## U8_BG95-M3
designator *  value BG95-M3
pins: 1 PSM_IND, 2 ADC1, 3 GND, 4 PCM_CLK, 5 PCM_SYNC, 6 PCM_DIN, 7 PCM_DOUT, 8 USB_VBUS (in), 9 USB_DP (io), 10 USB_DM (io), 11 RESERVED, 12 RESERVED, 13 RESERVED, 14 RESERVED, 15 PWRKEY (in), 16 RESERVED, 17 RESET_N, 18 W_DISABLE#, 19 AP_READY, 20 STATUS (out), 21 NET_STATUS, 22 DBG_RXD (in), 23 DBG_TXD (out), 24 ADC0, 25 GPIO1, 26 GPIO2, 27 GNSS_TXD, 28 GNSS_RXD, 29 VDD_EXT (out), 30 MAIN_DTR (in), 31 GND, 32 VBAT_BB, 33 VBAT_BB, 34 MAIN_RXD (in), 35 MAIN_TXD (out), 36 MAIN_CTS, 37 MAIN_RTS, 38 MAIN_DCD, 39 MAIN_RI (out), 40 I2C_SCL, 41 I2C_SDA, 42 USIM_DET, 43 USIM_VDD (out), 44 USIM_RST (out), 45 USIM_DATA (io), 46 USIM_CLK (out), 47 USIM_GND, 48 GND, 49 ANT_GNSS, 50 GND, 51 GNSS_LNA_EN, 52 VBAT_RF, 53 VBAT_RF, 54 GND, 55 GND, 56 ANT_WIFI, 57 RESERVED, 58 GND, 59 GND, 60 ANT_MAIN (io), 61 GND, 62 GND, 63 RESERVED, 64 GPIO3, 65 GPIO4, 66 GPIO5, 67 GND, 68 GND, 69 GND, 70 GND, 71 GND, 72 GND, 73 GND, 74 GND, 75 USB_BOOT (in), 76 RESERVED, 77 RESERVED, 78 RESERVED, 79 GND, 80 GND, 81 GND, 82 GND, 83 GRFC1, 84 GRFC2, 85 GPIO6, 86 GPIO7, 87 GPIO8, 88 GPIO9, 89 GND, 90 GND, 91 GND, 92 RESERVED, 93 RESERVED, 94 RESERVED, 95 RESERVED, 96 PON_TRIG, 97 RESERVED, 98 RESERVED, 99 RESERVED, 100 GND, 101 GND, 102 GND

## U9_MAX-M10S-00B
designator *  value MAX-M10S-00B
pins: 1 GND, 2 TXD (out), 3 RXD (in), 4 TIMEPULSE (out), 5 EXTINT, 6 V_BCKP, 7 V_IO, 8 VCC, 9 RESET_N, 10 GND, 11 RF_IN (in), 12 GND, 13 LNA_EN (out), 14 VCC_RF (out), 15 VIO_SEL, 16 SDA (in), 17 SCL (in), 18 SAFEBOOT_N

## U10_E22-900M22S
designator *  value E22-900M22S
pins: 1 GND, 2 GND, 3 GND, 4 GND, 5 GND, 6 RXEN (in), 7 TXEN (in), 8 DIO2, 9 VCC, 10 GND, 11 GND, 12 GND, 13 DIO1 (out), 14 BUSY (out), 15 NRST (in), 16 MISO (out), 17 MOSI (in), 18 SCK (in), 19 NSS (in), 20 GND, 21 ANT (io), 22 GND

## U11_MDBT50Q-P1MV2
designator *  value MDBT50Q-P1MV2
pins: 1 GND, 2 GND, 3 P1.10, 4 P1.11, 5 P1.12, 6 P1.13, 7 P1.14, 8 P1.15, 9 P0.03/AIN1, 10 P0.29/AIN5, 11 P0.02/AIN0, 12 P0.31/AIN7, 13 P0.28/AIN4, 14 P0.30/AIN6, 15 GND, 16 P0.27, 17 P0.00/XL1, 18 P0.01/XL2, 19 P0.26, 20 P0.04/AIN2, 21 P0.05/AIN3, 22 P0.06 (out), 23 P0.07/TRACECLK, 24 P0.08 (in), 25 P1.08, 26 P1.09/TRACEDATA3, 27 P0.11/TRACEDATA2, 28 VDD, 29 P0.12/TRACEDATA1, 30 VDDH, 31 DCCH, 32 VBUS, 33 GND, 34 D-, 35 D+, 36 P0.14, 37 P0.13, 38 P0.16, 39 P0.15 (in), 40 P0.18/nRESET (in), 41 P0.17, 42 P0.19, 43 P0.21, 44 P0.20, 45 P0.23, 46 P0.22, 47 P1.00/TRACEDATA0, 48 P0.24, 49 P0.25, 50 P1.02, 51 SWDIO (io), 52 P0.09/NFC1, 53 SWDCLK (in), 54 P0.10/NFC2, 55 GND, 56 P1.04, 57 P1.06, 58 P1.07, 59 P1.05, 60 P1.03, 61 P1.01

## U12_SDCIT2_32GB
designator *  value SDCIT2/32GB
pins: 1 DAT2 (io), 2 CD/DAT3 (io), 3 CMD (io), 4 VDD, 5 CLK (in), 6 VSS, 7 DAT0 (io), 8 DAT1 (io)

## U13_TS3A27518EPWR
designator *  value TS3A27518EPWR
pins: 1 NC2 (io), 2 NC1 (io), 3 N.C., 4 COM1 (io), 5 GND, 6 COM2 (io), 7 COM3 (io), 8 VCC, 9 COM4 (io), 10 COM5 (io), 11 NO1 (io), 12 COM6 (io), 13 NO2 (io), 14 IN2 (in), 15 NO3 (io), 16 NO6 (io), 17 NO4 (io), 18 NO5 (io), 19 NC5 (io), 20 EN (in), 21 NC4 (io), 22 NC6 (io), 23 NC3 (io), 24 IN1 (in)

## U14_ESDALC6V1-5P6
designator *  value ESDALC6V1-5P6
pins: 1 I/O1 (io), 2 GND, 3 I/O2 (io), 4 I/O3 (io), 5 I/O4 (io), 6 I/O5 (in)

## U15_ESDALC6V1-5P6
designator *  value ESDALC6V1-5P6
pins: 1 I/O1 (io), 2 GND, 3 I/O2 (io), 4 I/O3 (io), 5 I/O4 (io), 6 I/O5 (in)

## U16_SN74AXC8T245PWR
designator *  value SN74AXC8T245PWR
pins: 1 VCCA, 2 DIR1 (in), 3 A1 (in), 4 A2 (in), 5 A3 (in), 6 A4 (in), 7 A5 (out), 8 A6 (out), 9 A7, 10 A8, 11 DIR2 (in), 12 GND, 13 GND, 14 B8 (in), 15 B7 (in), 16 B6 (in), 17 B5 (in), 18 B4, 19 B3 (out), 20 B2 (out), 21 B1 (out), 22 OE (in), 23 VCCB, 24 VCCB

## U17_SN74LVC32APWR
designator *  value SN74LVC32APWR
pins: 1 1A (in), 2 1B (in), 3 1Y (out), 4 2A (in), 5 2B (in), 6 2Y (out), 7 GND, 8 3Y (out), 9 3A (in), 10 3B (in), 11 4Y, 12 4A (in), 13 4B (in), 14 VCC

## U18_SN74AXC1T45DRLR
designator *  value SN74AXC1T45DRLR
pins: 1 VCCA, 2 GND, 3 A (in), 4 B (out), 5 DIR (in), 6 VCCB

## U19_TPD4E05U06DQAR
designator *  value 4 channel 0.5 pF ESD
pins: 1, 2, 3, 4, 5, 6, 7, 8, 9, 10

## U20_TPD4E05U06DQAR
designator *  value 4 channel 0.5 pF ESD
pins: 1, 2, 3, 4, 5, 6, 7, 8, 9, 10

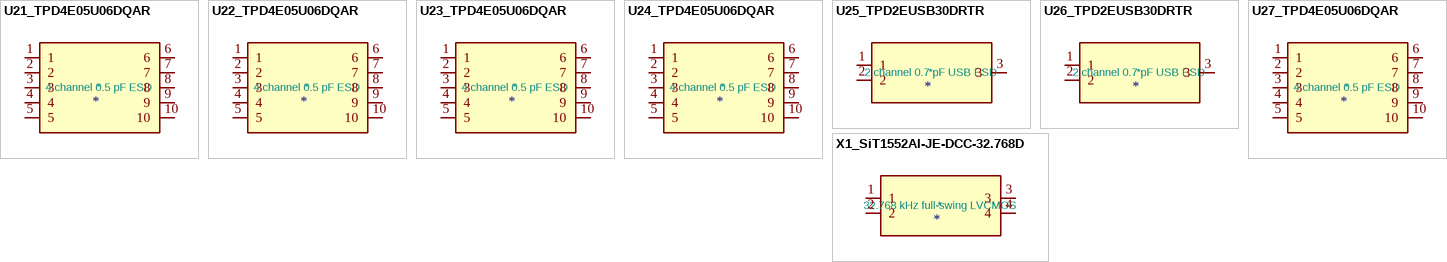
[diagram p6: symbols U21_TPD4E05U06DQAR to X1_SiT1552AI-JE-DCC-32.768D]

## U21_TPD4E05U06DQAR
designator *  value 4 channel 0.5 pF ESD
pins: 1, 2, 3, 4, 5, 6, 7, 8, 9, 10

## U22_TPD4E05U06DQAR
designator *  value 4 channel 0.5 pF ESD
pins: 1, 2, 3, 4, 5, 6, 7, 8, 9, 10

## U23_TPD4E05U06DQAR
designator *  value 4 channel 0.5 pF ESD
pins: 1, 2, 3, 4, 5, 6, 7, 8, 9, 10

## U24_TPD4E05U06DQAR
designator *  value 4 channel 0.5 pF ESD
pins: 1, 2, 3, 4, 5, 6, 7, 8, 9, 10

## U25_TPD2EUSB30DRTR
designator *  value 2 channel 0.7 pF USB ESD
pins: 1, 2, 3

## U26_TPD2EUSB30DRTR
designator *  value 2 channel 0.7 pF USB ESD
pins: 1, 2, 3

## U27_TPD4E05U06DQAR
designator *  value 4 channel 0.5 pF ESD
pins: 1, 2, 3, 4, 5, 6, 7, 8, 9, 10

## X1_SiT1552AI-JE-DCC-32.768D
designator *  value 32.768 kHz full-swing LVCMOS
pins: 1, 2, 3, 4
